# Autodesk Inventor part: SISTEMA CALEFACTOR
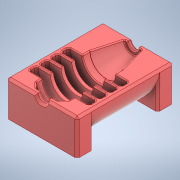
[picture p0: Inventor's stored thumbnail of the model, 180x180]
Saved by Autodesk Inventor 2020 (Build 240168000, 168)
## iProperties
Created: 2022-10
Part Number: SISTEMA CALEFACTOR
Material: Plástico PMMA
Document SubType Name: Modeling
Designer: SEBAS
Density: 1.188 g/cm^3
Appearance: Suave - Rojo
Author: SEBAS
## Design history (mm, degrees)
sketch "Boceto1"
  geometry: L1 (0, 0)-(25, 0); L2 (25, 0)-(25, -5); L3 (25, -5)-(23, -5); L4 (23, -5)-(18, -10); L5 (18, -10)-(18, -16); L6 (18, -16)-(5, -16); L7 (5, -16)-(5, -23); L8 (5, -23)-(18, -23); L9 (18, -23)-(18, -26); L10 (18, -26)-(5, -26); L11 (5, -26)-(5, -33); L12 (5, -33)-(18, -33); L13 (18, -33)-(18, -36); L14 (18, -36)-(5, -36); L15 (5, -36)-(5, -43); L16 (5, -43)-(18, -43); L17 (18, -43)-(18, -46); L18 (18, -46)-(5, -46); L19 (5, -46)-(5, -53); L20 (5, -53)-(18, -53); L21 (18, -53)-(18, -60); L22 (18, -60)-(25, -85); L23 (25, -85)-(25, -90); L24 (25, -90)-(0, -90); L25 (0, -90)-(0, 0); L26 (25, 0)-(33, 0); L27 (33, 0)-(33, -5); L28 (33, -5)-(25, -5); L29 (25, -5)-(25, 0); L30 (25, -90)-(33, -90); L31 (33, -90)-(33, -85); L32 (33, -85)-(25, -85); L33 (25, -85)-(25, -90); L34 (33, 0)-(33, -90)
  constraints: 68 end point, 15 perpendicular, 15 point on line, 7 collinear, 6 vertical alignment, 5 parallel, 3 horizontal, 1 vertical
  dimensions: "d0" = 80 vertical distance of L22.end L3.end; "d1" = 5 distance from line of L25 L6.end; "d2" = 3 distance of L8.end L9.end; "d3" = 7 distance of L6.end L7.end; "d4" = 7 distance of L20.end L21.end; "d5" = 25 vertical distance of L22.end L21.end; "d6" = 5 horizontal distance of L4.end L3.end; "d7" = 5 horizontal distance of L3.end L4.end; "d9" = 5 distance of L1.end L2.end; "d10" = 7 horizontal distance of L22.end L21.end; "d11" = 15 horizontal distance of L5.end L26.end
revolve "Revolución1" sketch "Boceto1" stored, may be unused: angle "d12" = 180 deg
sketch "Boceto2"
  geometry: L1 (-33, 0)-(33, 0) reference; C1 r 5 at (0, 0); 2 further points
  constraints: 1 centre point, 1 coincident, 1 midpoint
  dimensions: "d15" = 10 diameter of C1
extrude "Extrusión1" cut sketch "Boceto2" stored distance "d16" = 10; taper "d17" = 0 deg
sketch "Boceto3"
  geometry: L1 (33, -90)-(33, 0) reference; L2 (33, 0)-(5, 0) reference; L3 (-33, 0)-(-33, -90) reference; L4 (33, 0)-(-33, 0); L5 (-33, 0)-(-33, -90); L6 (-33, -90)-(33, -90); L7 (33, -90)-(33, 0); L8 (33, 0)-(-33, 0); L9 (-33, 0)-(-33, -15); L10 (-33, -15)-(33, -15); L11 (33, -15)-(33, 0); L12 (33, -90)-(-33, -90); L13 (-33, -90)-(-33, -75); L14 (-33, -75)-(33, -75); L15 (33, -75)-(33, -90); 8 further points
  constraints: 24 end point, 6 parallel, 3 horizontal, 3 perpendicular, 2 point on line
  dimensions: "d18" = 15 distance between parallel lines of L6 L14; "d19" = 15 distance between parallel lines of L2 L10
extrude "Extrusión2" join sketch "Boceto3" distance "d20" = 10; taper "d21" = 0 deg
fillet "Empalme4" dims "d23" = 2
fillet "Empalme5" dims "d24" = 1
sketch "Boceto4"
  geometry: L1 (-33, 15)-(-33, 0) reference; L2 (-33, 15)-(-23.664, 15); L3 (-23.664, 15)-(-23.664, 0); L4 (-23.664, 0)-(-33, 0); L5 (-33, 0)-(-33, 15); L6 (33, 0)-(33, 15) reference; L7 (33, 0)-(23.664, 0); L8 (23.664, 0)-(23.664, 15); L9 (23.664, 15)-(33, 15); L10 (33, 15)-(33, 0); L11 (33, 75)-(23.664, 75); L12 (23.664, 75)-(23.664, 90); L13 (23.664, 90)-(33, 90); L14 (33, 90)-(33, 75); L15 (-33, 75)-(-23.664, 75); L16 (-23.664, 75)-(-23.664, 90); L17 (-23.664, 90)-(-33, 90); L18 (-33, 90)-(-33, 75); 6 further points
  constraints: 32 end point, 8 parallel, 4 coincident, 4 horizontal, 4 perpendicular
extrude "Extrusión3" join sketch "Boceto4" stored distance "d25" = 10; taper "d26" = 0 deg
chamfer "Chaflán1" distance "d27" = 2; stored, may be unused: second distance "d28" = 2, angle "d29" = 45 deg
node "Sólido1"
